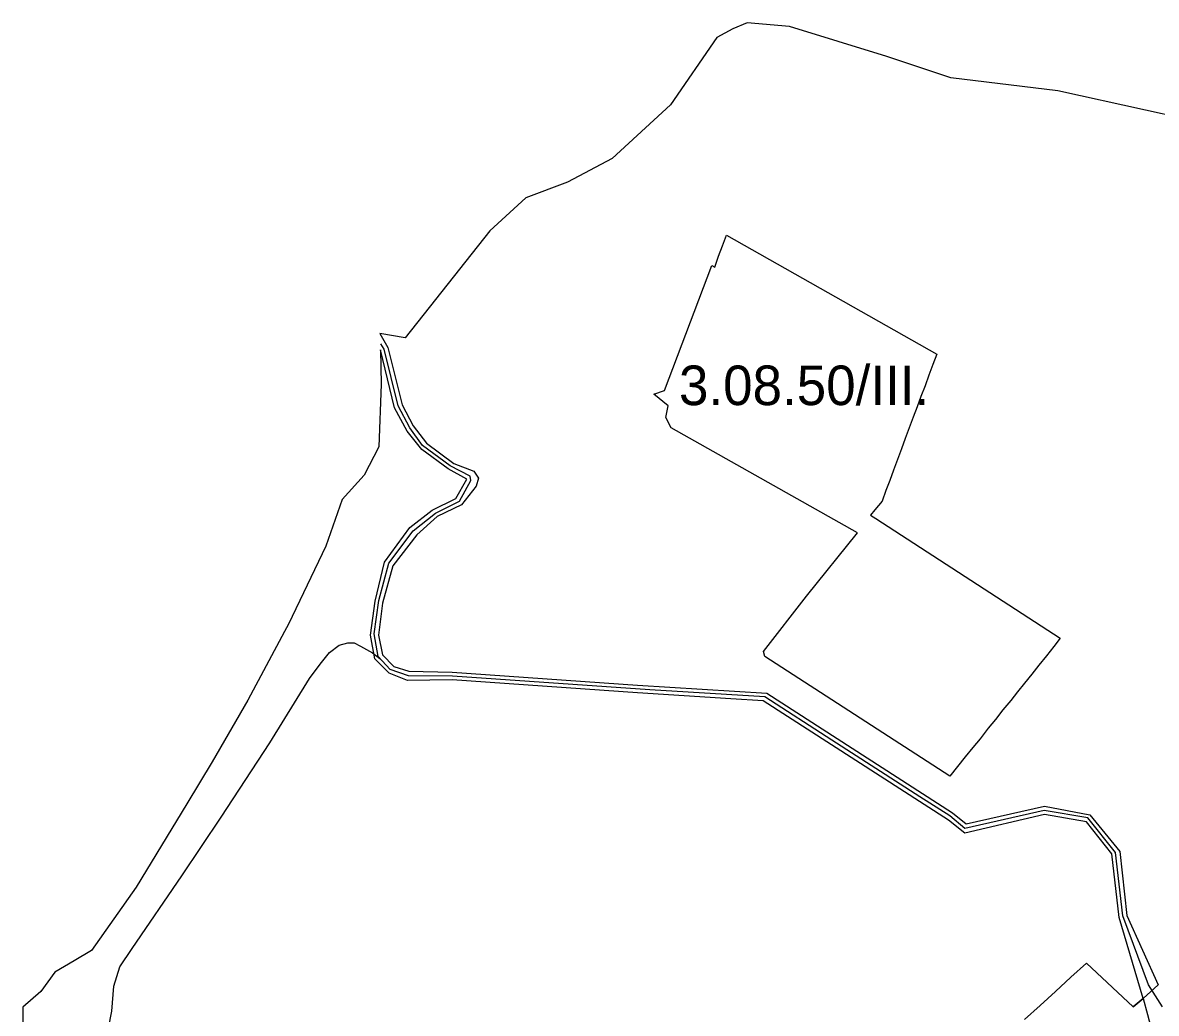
# Model space of a CAD drawing. Extents: x -555509 to -553014, y -1186753 to -1182560.
# Drawn here: x -555128 to -554556, y -1183061 to -1182560 of the extents above; entities that cross this region are included whole.
import ezdxf

# ---------------------------------------------------------------- set-up
doc = ezdxf.new("R2010")
doc.units = 0
for name, color, linetype in [('Level 29', 7, 'Continuous'), ('pěší_tr', 7, 'Continuous'), ('ZM2_KOO_legenda', 7, 'Continuous')]:
    doc.layers.add(name, color=color, linetype=linetype)

msp = doc.modelspace()

# ---------------------------------------------------------------- linework, layer by layer
at = {"layer": 'Level 29'}
for points in [[(-554809.56, -1182748.02), (-554804.24, -1182746.09), (-554780.38, -1182683.03), (-554778.75, -1182683.79), (-554776.86, -1182678.36), (-554774.88, -1182673.03), (-554772.9, -1182667.71), (-554666.73, -1182727.7), (-554668.72, -1182733.01), (-554670.72, -1182738.37), (-554672.62, -1182743.74), (-554674.7, -1182749.11), (-554676.68, -1182754.39), (-554678.64, -1182759.62), (-554680.59, -1182764.96), (-554682.62, -1182770.33), (-554684.58, -1182775.61), (-554686.46, -1182780.94), (-554688.52, -1182786.3), (-554690.42, -1182791.52), (-554692.44, -1182796.71), (-554694.32, -1182802.05), (-554698.03, -1182806.37), (-554700.16, -1182809.13), (-554697.56, -1182810.81), (-554604.33, -1182871.18), (-554607.57, -1182875.37), (-554611.33, -1182880.08), (-554615.1, -1182884.8), (-554618.76, -1182889.39), (-554622.34, -1182893.87), (-554625.97, -1182898.29), (-554629.38, -1182902.63), (-554633.35, -1182907.44), (-554637.08, -1182912.33), (-554640.7, -1182916.69), (-554644.85, -1182921.99), (-554648.51, -1182926.36), (-554652.29, -1182931.05), (-554660.11, -1182940.98), (-554753.5, -1182880.52), (-554754.24, -1182878), (-554732.55, -1182850.06), (-554706.8, -1182817.93), (-554800.79, -1182765), (-554803.48, -1182759.79), (-554802.43, -1182753.89), (-554809.56, -1182748.02)], [(-554554.89, -1183046.35), (-554562.53, -1183053.13), (-554567.43, -1183057.47), (-554591.15, -1183035.39), (-554598.91, -1183042.47), (-554606.78, -1183049.62), (-554614.53, -1183056.65), (-554622.33, -1183063.77)], [(-554562.53, -1183053.13), (-554560.35, -1183061.34), (-554557.75, -1183070.88), (-554544.62, -1183099.75)]]:
    msp.add_lwpolyline(points, dxfattribs=at)
at = {"layer": 'pěší_tr'}
for points in [[(-554552.63, -1183057.31), (-554559.76, -1183046.21), (-554572.78, -1183011.44), (-554576.41, -1182979.45), (-554590.45, -1182961.98), (-554612.38, -1182958.28), (-554652.52, -1182967.32), (-554660.13, -1182960.95), (-554675.34, -1182951.29), (-554719.67, -1182922.79), (-554753.51, -1182900.86), (-554811.61, -1182897.3), (-554911.29, -1182890.31), (-554933.56, -1182890.25), (-554942.74, -1182887.03), (-554948.91, -1182880.52), (-554950.82, -1182868.94), (-554948.43, -1182852.15), (-554943.49, -1182833.31), (-554931.09, -1182817.01), (-554919.93, -1182808.1), (-554907.8, -1182802), (-554901.98, -1182791.59), (-554902.39, -1182789.47), (-554912.39, -1182784.19), (-554926.37, -1182773.98), (-554932.84, -1182765.06), (-554938.77, -1182753.81), (-554945.76, -1182725.17), (-554947.4, -1182722.5)], [(-555085.06, -1183068.12), (-555083.35, -1183059.56), (-555082.32, -1183046.88), (-555079.31, -1183037.16), (-555073.14, -1183027.97), (-555047.93, -1182991.18), (-555028.06, -1182961.66), (-555003.47, -1182924.04), (-554983.53, -1182891.5), (-554978.19, -1182884.31), (-554973.42, -1182878.43), (-554968.53, -1182874.77), (-554964.14, -1182873.6), (-554960.89, -1182873.53), (-554957.77, -1182875.25), (-554951.67, -1182878.64), (-554947.98, -1182881.49)]]:
    msp.add_lwpolyline(points, dxfattribs=at)
at = {"layer": 'ZM2_KOO_legenda'}
for p, q in [((-554762.39, -1182560.36), (-554769.7, -1182563.46)), ((-554741.15, -1182562.37), (-554762.39, -1182560.36)), ((-554769.7, -1182563.46), (-554777.78, -1182567.93)), ((-554691.98, -1182577.49), (-554741.15, -1182562.37)), ((-554777.78, -1182567.93), (-554801.19, -1182601.82)), ((-554659.55, -1182588.17), (-554691.98, -1182577.49)), ((-554605.6, -1182594.73), (-554659.55, -1182588.17)), ((-554561.36, -1182604.56), (-554605.6, -1182594.73)), ((-554801.19, -1182601.82), (-554830.68, -1182628.91)), ((-554517.15, -1182614.23), (-554561.36, -1182604.56)), ((-554830.68, -1182628.91), (-554853.13, -1182640.85)), ((-554853.13, -1182640.85), (-554874.23, -1182648.75)), ((-554874.23, -1182648.75), (-554892.39, -1182665.45)), ((-554892.39, -1182665.45), (-554935.19, -1182719.49)), ((-554774.88, -1182673.03), (-554772.9, -1182667.71)), ((-554772.9, -1182667.71), (-554666.73, -1182727.7)), ((-554776.86, -1182678.36), (-554774.88, -1182673.03)), ((-554778.75, -1182683.79), (-554776.86, -1182678.36)), ((-554804.24, -1182746.09), (-554780.38, -1182683.03)), ((-554780.38, -1182683.03), (-554778.75, -1182683.79)), ((-554935.19, -1182719.49), (-554947.92, -1182717.4)), ((-554947.92, -1182717.4), (-554943.97, -1182724.38)), ((-554940.62, -1182754.85), (-554947.66, -1182725.61)), ((-554947.66, -1182725.61), (-554947.27, -1182743)), ((-554943.97, -1182724.38), (-554936.78, -1182753.4)), ((-554666.73, -1182727.7), (-554668.72, -1182733.01)), ((-554668.72, -1182733.01), (-554670.72, -1182738.37)), ((-554947.27, -1182743), (-554948.45, -1182774.52)), ((-554672.62, -1182743.74), (-554674.7, -1182749.11)), ((-554670.72, -1182738.37), (-554672.62, -1182743.74)), ((-554809.56, -1182748.02), (-554804.24, -1182746.09)), ((-554802.43, -1182753.89), (-554809.56, -1182748.02)), ((-554674.7, -1182749.11), (-554676.68, -1182754.39)), ((-554934.1, -1182766.63), (-554940.62, -1182754.85)), ((-554936.78, -1182753.4), (-554931.17, -1182763.9)), ((-554803.48, -1182759.79), (-554802.43, -1182753.89)), ((-554676.68, -1182754.39), (-554678.64, -1182759.62)), ((-554800.79, -1182765), (-554803.48, -1182759.79)), ((-554678.64, -1182759.62), (-554680.59, -1182764.96)), ((-554926.76, -1182775.87), (-554934.1, -1182766.63)), ((-554931.17, -1182763.9), (-554924.38, -1182772.75)), ((-554706.8, -1182817.93), (-554800.79, -1182765)), ((-554680.59, -1182764.96), (-554682.62, -1182770.33)), ((-554682.62, -1182770.33), (-554684.58, -1182775.61)), ((-554948.45, -1182774.52), (-554955.83, -1182788.89)), ((-554913.5, -1182785.74), (-554926.76, -1182775.87)), ((-554924.38, -1182772.75), (-554910.58, -1182783)), ((-554684.58, -1182775.61), (-554686.46, -1182780.94)), ((-554910.58, -1182783), (-554900.45, -1182786.81)), ((-554686.46, -1182780.94), (-554688.52, -1182786.3)), ((-554955.83, -1182788.89), (-554967.08, -1182801.1)), ((-554903.99, -1182790.92), (-554913.5, -1182785.74)), ((-554900.45, -1182786.81), (-554898.1, -1182790.37)), ((-554688.52, -1182786.3), (-554690.42, -1182791.52)), ((-554909.65, -1182800.72), (-554903.99, -1182790.92)), ((-554899.28, -1182794.36), (-554906.76, -1182803.83)), ((-554898.1, -1182790.37), (-554899.28, -1182794.36)), ((-554690.42, -1182791.52), (-554692.44, -1182796.71)), ((-554967.08, -1182801.1), (-554975.33, -1182824.78)), ((-554921.54, -1182806.61), (-554909.65, -1182800.72)), ((-554692.44, -1182796.71), (-554694.32, -1182802.05)), ((-554932.8, -1182815.31), (-554921.54, -1182806.61)), ((-554906.76, -1182803.83), (-554918.98, -1182809.69)), ((-554698.03, -1182806.37), (-554700.16, -1182809.13)), ((-554694.32, -1182802.05), (-554698.03, -1182806.37)), ((-554918.98, -1182809.69), (-554929.32, -1182818.98)), ((-554700.16, -1182809.13), (-554697.56, -1182810.81)), ((-554697.56, -1182810.81), (-554604.33, -1182871.18)), ((-554945.64, -1182832.89), (-554932.8, -1182815.31)), ((-554732.55, -1182850.06), (-554706.8, -1182817.93)), ((-554929.32, -1182818.98), (-554941.41, -1182834.68)), ((-554975.33, -1182824.78), (-554994.15, -1182864.15)), ((-554950.4, -1182852.48), (-554945.64, -1182832.89)), ((-554941.41, -1182834.68), (-554946.56, -1182853.59)), ((-554952.64, -1182869.63), (-554950.4, -1182852.48)), ((-554754.24, -1182878), (-554732.55, -1182850.06)), ((-554946.56, -1182853.59), (-554948.65, -1182869.74)), ((-554994.15, -1182864.15), (-554996.15, -1182867.89)), ((-554996.15, -1182867.89), (-555014.68, -1182902.52)), ((-554950.54, -1182881.59), (-554952.64, -1182869.63)), ((-554948.65, -1182869.74), (-554946.64, -1182879.66)), ((-554607.57, -1182875.37), (-554611.33, -1182880.08)), ((-554604.33, -1182871.18), (-554607.57, -1182875.37)), ((-554946.64, -1182879.66), (-554940.94, -1182885.43)), ((-554753.5, -1182880.52), (-554754.24, -1182878)), ((-554660.11, -1182940.98), (-554753.5, -1182880.52)), ((-554611.33, -1182880.08), (-554615.1, -1182884.8)), ((-554943.35, -1182888.88), (-554950.54, -1182881.59)), ((-554940.94, -1182885.43), (-554933.31, -1182887.88)), ((-554615.1, -1182884.8), (-554618.76, -1182889.39)), ((-554934.06, -1182892.53), (-554943.35, -1182888.88)), ((-554911.41, -1182892.31), (-554934.06, -1182892.53)), ((-554933.31, -1182887.88), (-554911.46, -1182888.34)), ((-554911.46, -1182888.34), (-554817.78, -1182894.93)), ((-554817.9, -1182898.85), (-554911.41, -1182892.31)), ((-554618.76, -1182889.39), (-554622.34, -1182893.87)), ((-554817.78, -1182894.93), (-554752.59, -1182899.05)), ((-554625.97, -1182898.29), (-554629.38, -1182902.63)), ((-554622.34, -1182893.87), (-554625.97, -1182898.29)), ((-555014.68, -1182902.52), (-555032.66, -1182933.68)), ((-554770.63, -1182901.89), (-554817.9, -1182898.85)), ((-554754.34, -1182902.81), (-554770.63, -1182901.89)), ((-554660.79, -1182963.07), (-554754.34, -1182902.81)), ((-554752.59, -1182899.05), (-554658.81, -1182959.37)), ((-554629.38, -1182902.63), (-554633.35, -1182907.44)), ((-554633.35, -1182907.44), (-554637.08, -1182912.33)), ((-554637.08, -1182912.33), (-554640.7, -1182916.69)), ((-554640.7, -1182916.69), (-554644.85, -1182921.99)), ((-554648.51, -1182926.36), (-554652.29, -1182931.05)), ((-554644.85, -1182921.99), (-554648.51, -1182926.36)), ((-554652.29, -1182931.05), (-554660.11, -1182940.98)), ((-555032.66, -1182933.68), (-555045.47, -1182954.8)), ((-555045.47, -1182954.8), (-555071.07, -1182997.01)), ((-554658.81, -1182959.37), (-554651.88, -1182965)), ((-554612.31, -1182960.24), (-554652.57, -1182969.72)), ((-554651.88, -1182965), (-554612.24, -1182956.03)), ((-554591, -1182963.93), (-554612.31, -1182960.24)), ((-554612.24, -1182956.03), (-554589.32, -1182960.43)), ((-554589.32, -1182960.43), (-554574.33, -1182979.01)), ((-554652.57, -1182969.72), (-554660.79, -1182963.07)), ((-554578.26, -1182980.06), (-554591, -1182963.93)), ((-554574.6, -1183012.24), (-554578.26, -1182980.06)), ((-554574.33, -1182979.01), (-554570.74, -1183011.26)), ((-555071.07, -1182997.01), (-555093.69, -1183029)), ((-554562.53, -1183053.13), (-554574.6, -1183012.24)), ((-554570.74, -1183011.26), (-554554.89, -1183046.35)), ((-555093.69, -1183029), (-555102.43, -1183034.15)), ((-555102.43, -1183034.15), (-555112.14, -1183039.88)), ((-554598.91, -1183042.47), (-554591.15, -1183035.39)), ((-554591.15, -1183035.39), (-554567.43, -1183057.47)), ((-555112.14, -1183039.88), (-555119.21, -1183049.69)), ((-554606.78, -1183049.62), (-554598.91, -1183042.47)), ((-555119.21, -1183049.69), (-555128.37, -1183057.57)), ((-554614.53, -1183056.65), (-554606.78, -1183049.62)), ((-554567.43, -1183057.47), (-554562.53, -1183053.13)), ((-555128.37, -1183057.57), (-555128.31, -1183071)), ((-554622.33, -1183063.77), (-554614.53, -1183056.65))]:
    msp.add_line(p, q, dxfattribs=at)

# ---------------------------------------------------------------- texts
at = {"layer": 'Level 29'}
msp.add_text('3.08.50/III.', height=20, dxfattribs=at).set_placement((-554796.91, -1182753.51))

doc.saveas('drawing.dxf')
